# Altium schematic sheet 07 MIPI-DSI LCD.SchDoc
size 420 x 297 mm; DocumentNumber: 7; SheetNumber: 7; SheetTotal: 12
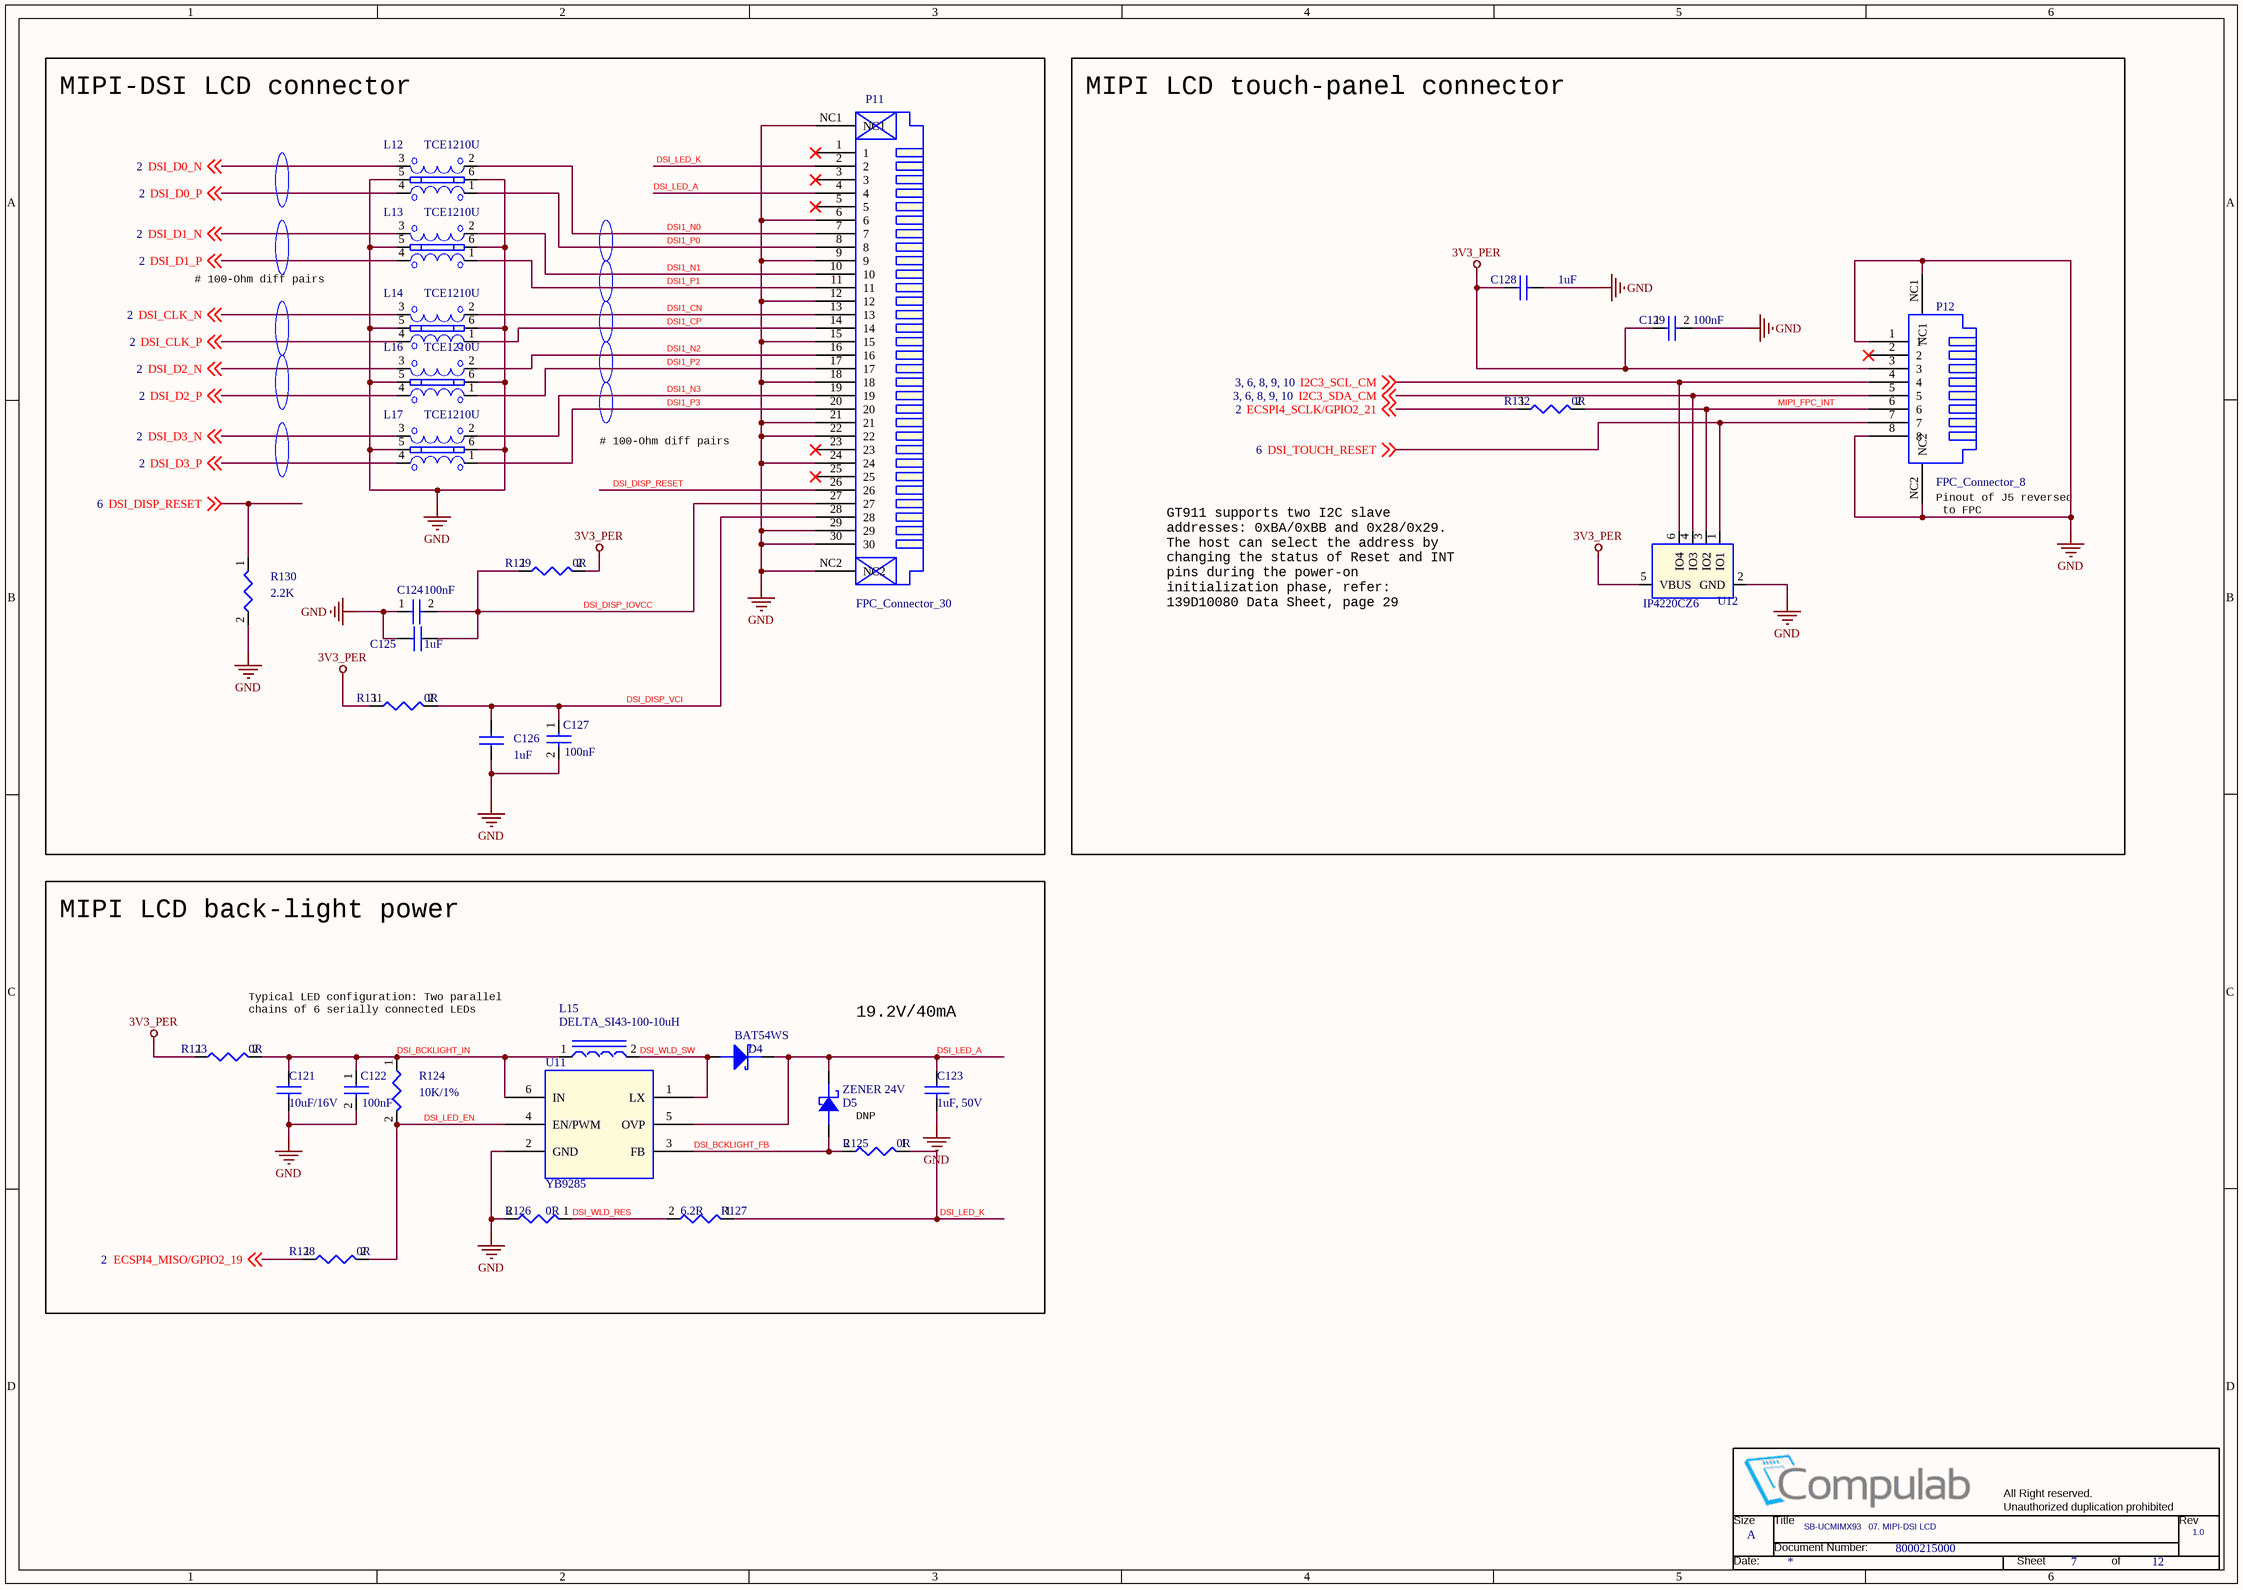
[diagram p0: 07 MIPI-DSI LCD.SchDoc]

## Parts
*  Title: SB-UCMIMX93   07. MIPI-DSI LCD  Doc: 8000215000  RevCode: 1.0  Page Size: A  Page Number: 7  Page Count: 12  (hidden comment: CompuLabTitleBlk)  (graphical)
C121  10uF/16V  [RC0603]
C122  100nF  [RC0402]
C123  1uF, 50V  [RC0603]
C124  100nF  [RC0402]
C125  1uF  [RC0402]
C126  1uF  [RC0402]
C127  100nF  [RC0402]
C128  1uF  [RC0402]
C129  100nF  [RC0402]
D4  BAT54WS  [SOD-323]
D5  ZENER 24V  [SOD-123]
L12  TCE1210U  [EMI1012-ESD]
L13  TCE1210U  [EMI1012-ESD]
L14  TCE1210U  [EMI1012-ESD]
L15  DELTA_SI43-100-10uH  [IND4x4x2_5]
L16  TCE1210U  [EMI1012-ESD]
L17  TCE1210U  [EMI1012-ESD]
P11  FPC_Connector_30  [FPC_30]
P12  FPC_Connector_8  [FPC_8]
R123  0R  [RC0402]
R124  10K/1%  [RC0402]
R125  0R  [RC0402]
R126  0R  [RC0402]
R127  6.2R  [RC0402]
R128  0R  [RC0402]
R129  0R  [RC0402]
R130  2.2K  [RC0402]
R131  0R  [RC0402]
R132  0R  [RC0402]
U11  YB9285  [SOT23-6L]
U12  IP4220CZ6  [SOT23-6L]

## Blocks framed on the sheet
MIPI-DSI LCD connector: C124-C127 L12-L14 L16 L17 P11 R129-R131
MIPI LCD touch-panel connector: C128 C129 P12 R132 U12
MIPI LCD back-light power: C121-C123 D4 D5 L15 R123-R128 U11

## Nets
3V3_PER: C128.1 C129.1 P12.3 R123.1 R129.2 R131.1 U12.5(VBUS)
GND: C121.2 C122.2 C123.2 C124.1 C125.2 C126.1 C127.2 C128.2 C129.2 L12.5(GND) L12.6(GND) L13.5(GND) L13.6(GND) L14.5(GND) L14.6(GND) L16.5(GND) L16.6(GND) L17.5(GND) L17.6(GND) P11.6 P11.9 P11.12 P11.15 P11.18 P11.21 P11.22 P11.24 P11.29 P11.30 P11.NC1 P11.NC2 P12.1 P12.8 P12.NC1 P12.NC2 R126.2 R130.2 U11.2(GND) U12.2(GND)
DSI1_CN: L14.2 P11.13
DSI1_CP: L14.1 P11.14
DSI1_N0: L12.2 P11.7
DSI1_N1: L13.2 P11.10
DSI1_N2: L16.2 P11.16
DSI1_N3: L17.2 P11.19
DSI1_P0: L12.1 P11.8
DSI1_P1: L13.1 P11.11
DSI1_P2: L16.1 P11.17
DSI1_P3: L17.1 P11.20
DSI_BCKLIGHT_FB: D5.2(ANODE) R125.2 U11.3(FB)
DSI_BCKLIGHT_IN: C121.1 C122.1 L15.1 R123.2 R124.1 U11.6(IN)
DSI_CLK_N: L14.3 ; off-sheet DSI_CLK_N
DSI_CLK_P: L14.4 ; off-sheet DSI_CLK_P
DSI_D0_N: L12.3 ; off-sheet DSI_D0_N
DSI_D0_P: L12.4 ; off-sheet DSI_D0_P
DSI_D1_N: L13.3 ; off-sheet DSI_D1_N
DSI_D1_P: L13.4 ; off-sheet DSI_D1_P
DSI_D2_N: L16.3 ; off-sheet DSI_D2_N
DSI_D2_P: L16.4 ; off-sheet DSI_D2_P
DSI_D3_N: L17.3 ; off-sheet DSI_D3_N
DSI_D3_P: L17.4 ; off-sheet DSI_D3_P
DSI_DISP_IOVCC: C124.2 C125.1 P11.27 R129.1
DSI_DISP_RESET: P11.26 R130.1 ; off-sheet DSI_DISP_RESET
DSI_DISP_VCI: C126.2 C127.1 P11.28 R131.2
DSI_LED_A: C123.1 D4.CATHODE D5.1(CATHODE) P11.4 U11.5(OVP)
DSI_LED_EN: R124.2 R128.2 U11.4(EN/PWM)
DSI_LED_K: P11.2 R125.1 R127.1
DSI_TOUCH_RESET: P12.7 U12.1(IO1) ; off-sheet DSI_TOUCH_RESET
DSI_WLD_RES: R126.1 R127.2
DSI_WLD_SW: D4.ANODE L15.2 U11.1(LX)
ECSPI4_MISO/GPIO2_19: R128.1 ; off-sheet ECSPI4_MISO/GPIO2_19
ECSPI4_SCLK/GPIO2_21: R132.1 ; off-sheet ECSPI4_SCLK/GPIO2_21
I2C3_SCL_CM: P12.4 U12.6(IO4) ; off-sheet I2C3_SCL_CM
I2C3_SDA_CM: P12.5 U12.4(IO3) ; off-sheet I2C3_SDA_CM
MIPI_FPC_INT: P12.6 R132.2 U12.3(IO2)

Not connected (* = marked no-connect by the designer): P11 1* 3* 5* 23* 25*; P12 2*

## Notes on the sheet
- # 100-Ohm diff pairs
- (near P12) Pinout of J5 reversed
  to FPC
- GT911 supports two I2C slave
  addresses: 0xBA/0xBB and 0x28/0x29.
  The host can select the address by
  changing the status of Reset and INT
  pins during the power-on
  initialization phase, refer:
  139D10080 Data Sheet, page 29
- Typical LED configuration: Two parallel
  chains of 6 serially connected LEDs
- 19.2V/40mA
- DNP

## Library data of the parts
C121 = 10uF,6.3V,0603,20%X5R_Dup1: P/N: 151C10610S
C122 C124 C127 C129 = 100nF, 10V, X7R, 10%, 0402_Dup1: P/N: 151B10400S
C123 = 1uF,X5R,6.3V,0402: P/N: 151D10510S
C125 C126 C128 = 1uF,X5R,6.3V,0402: P/N: 151B10500S
D4 = BAT54WS_0_Dup1: P/N: 130E05402S
D5 = ZENER 24V 500mW SOD-123: P/N: 130B24000S; CLABCONF0: DNP
L12-L14 L16 L17 = ESD_CHOKE_DIFFx2_10: P/N: 142D11801S
L15 = INC DELTA SI43-100, 10uH: P/N: 147A10001S; CLABCONF1: <null>
P11 = FPC_Connector_0: P/N: 182P03002S
P12 = FPC_Connector_4: P/N: 182P00802S
R123 R125 R129 R131 R132 = 0R, 0402: P/N: 161C00005S
R124 = 10K,1%,0402,1/16W_0_Dup1: P/N: 161C10021S
R126 = 2.2R,5%,0402,1/16W: P/N: 161C00005S
R127 = 2.2R,5%,0402,1/16W: P/N: 161C06R25S
R128 = 0R, 0402: P/N: 161C00005S; CLABCONF0: DNP
R130 = 2.2K,5%,0402.1/16W: P/N: 161C22015S
U11 = AIC1647_0: P/N: 123C40000S
U12 = IP4220CZ6_0: P/N: 132D42200S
